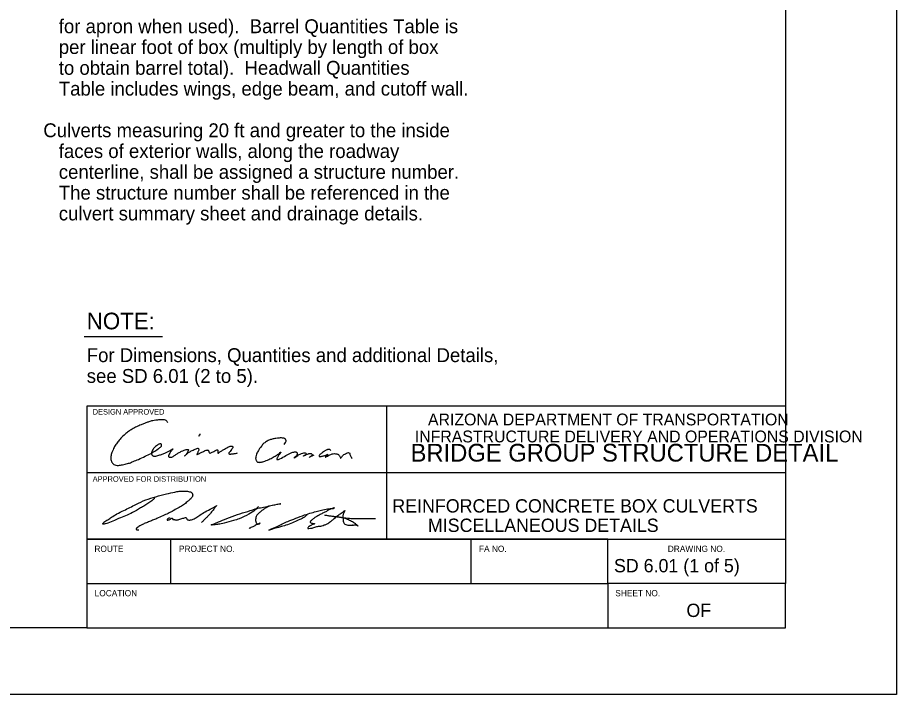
# Model space of a CAD drawing. Extents: x -0.08 to 2.83, y -0.03 to 1.92.
# Drawn here: x 2.009 to 2.833, y 0 to 0.635 of the extents above; entities that cross this region are included whole.
import ezdxf

# ---------------------------------------------------------------- set-up
doc = ezdxf.new("R2010")
doc.units = 0
for name, color, linetype in [('55', 7, 'Continuous'), ('57', 7, 'Continuous'), ('62', 7, 'Continuous'), ('63', 7, 'Continuous')]:
    doc.layers.add(name, color=color, linetype=linetype)

msp = doc.modelspace()

# ---------------------------------------------------------------- linework, layer by layer
at = {"layer": '55'}
for points in [[(2.15001, 0.25543), (2.14758, 0.25741), (2.14617, 0.25785), (2.14423, 0.25794), (2.14225, 0.25776), (2.1402, 0.25761), (2.13722, 0.2572), (2.13461, 0.25674), (2.13312, 0.25633), (2.13139, 0.2557), (2.1309, 0.25548), (2.1279, 0.25446), (2.12484, 0.2532), (2.1206, 0.25132), (2.11648, 0.24906), (2.11297, 0.24683), (2.10987, 0.24445), (2.10588, 0.24062), (2.10299, 0.237), (2.10059, 0.23378), (2.09857, 0.22978), (2.09735, 0.22698), (2.09658, 0.22347), (2.09632, 0.22083), (2.0965, 0.22021), (2.09681, 0.21951), (2.09723, 0.21833), (2.098, 0.21721), (2.09936, 0.21582), (2.101, 0.2152), (2.10355, 0.21505), (2.10736, 0.21566), (2.10994, 0.21625), (2.11399, 0.21726), (2.11746, 0.21865), (2.1224, 0.22067), (2.12858, 0.22356), (2.13414, 0.22632), (2.14122, 0.23075), (2.14355, 0.23265), (2.1438, 0.23291), (2.14403, 0.23351), (2.14403, 0.23426), (2.14395, 0.23467), (2.14366, 0.23506), (2.14306, 0.23523), (2.14231, 0.23519), (2.14138, 0.23496), (2.14015, 0.23417), (2.13831, 0.23262), (2.1366, 0.23096), (2.1355, 0.22937), (2.13485, 0.2278), (2.13469, 0.22641), (2.13471, 0.22546), (2.13499, 0.22483), (2.13551, 0.2243), (2.13614, 0.22393), (2.13712, 0.22378), (2.13865, 0.22378), (2.14061, 0.22424), (2.1439, 0.22538), (2.14709, 0.22656), (2.14964, 0.22791), (2.15235, 0.22918), (2.1548, 0.23064), (2.15321, 0.22863), (2.15278, 0.22814), (2.15212, 0.22718), (2.15124, 0.22569), (2.15055, 0.22402), (2.15062, 0.22327), (2.15113, 0.2227), (2.15171, 0.22264), (2.15353, 0.2229), (2.15492, 0.22351), (2.15731, 0.22511), (2.15997, 0.22683), (2.16276, 0.22826), (2.16513, 0.22931), (2.1672, 0.22997), (2.16877, 0.23003), (2.16885, 0.23001), (2.16905, 0.22994), (2.16916, 0.22971), (2.16921, 0.22923), (2.16902, 0.22873), (2.16846, 0.22743), (2.1677, 0.22608), (2.16569, 0.22382), (2.16628, 0.22431), (2.16828, 0.22641), (2.16883, 0.2268), (2.16988, 0.2275), (2.1711, 0.22812), (2.17281, 0.229), (2.17455, 0.2298), (2.17652, 0.23053), (2.17805, 0.23107), (2.17845, 0.23099), (2.17884, 0.23056), (2.17886, 0.22947), (2.17831, 0.22798), (2.17796, 0.22723), (2.17731, 0.22578), (2.17716, 0.22546), (2.17716, 0.22538), (2.17753, 0.22539), (2.17821, 0.22565), (2.17895, 0.22596), (2.18003, 0.22647), (2.18113, 0.22707), (2.18425, 0.22854), (2.18595, 0.22925), (2.18701, 0.22947), (2.18751, 0.22945), (2.18764, 0.22938), (2.18777, 0.22927), (2.18805, 0.22878), (2.18849, 0.22777), (2.18919, 0.22648), (2.1903, 0.2268), (2.19162, 0.22742), (2.19305, 0.22818), (2.19472, 0.22898), (2.1958, 0.22955), (2.19618, 0.2297), (2.19652, 0.22948), (2.19677, 0.22899), (2.19681, 0.22851), (2.19688, 0.22708), (2.19689, 0.22654), (2.19699, 0.2265), (2.19794, 0.22713), (2.20054, 0.22882), (2.20306, 0.23041), (2.20516, 0.23164), (2.20697, 0.23255), (2.20839, 0.23299), (2.21006, 0.23312), (2.2106, 0.23289), (2.21082, 0.23247), (2.2109, 0.23199), (2.21081, 0.23152), (2.2104, 0.23086), (2.20965, 0.2299), (2.20831, 0.22816), (2.20712, 0.22678), (2.20699, 0.22618), (2.20715, 0.22586), (2.2085, 0.22567), (2.20942, 0.22576), (2.21055, 0.22588), (2.21161, 0.22603), (2.21247, 0.22616), (2.21418, 0.22636), (2.21539, 0.22668)], [(2.17986, 0.24471), (2.17999, 0.24419), (2.17945, 0.24328), (2.17891, 0.24254), (2.18016, 0.24389), (2.18061, 0.24401)], [(2.25913, 0.23472), (2.26029, 0.23637), (2.26076, 0.23774), (2.26076, 0.23856), (2.26062, 0.23911), (2.26004, 0.23992), (2.25945, 0.24026), (2.2583, 0.24058), (2.25644, 0.2408), (2.25422, 0.2407), (2.25114, 0.2404), (2.24777, 0.23963), (2.2448, 0.23864), (2.24155, 0.23685), (2.23882, 0.23456), (2.2377, 0.23304), (2.2365, 0.23153), (2.23482, 0.22905), (2.23317, 0.22562), (2.23251, 0.22313), (2.2323, 0.22157), (2.2325, 0.22061), (2.23275, 0.2199), (2.23334, 0.21882), (2.23414, 0.21819), (2.23498, 0.21801), (2.2361, 0.21789), (2.23696, 0.21795), (2.23781, 0.21809), (2.23899, 0.21844), (2.24106, 0.21913), (2.24338, 0.21998), (2.24568, 0.22106), (2.24791, 0.22222), (2.25148, 0.22431), (2.25408, 0.22593), (2.25528, 0.22699), (2.25596, 0.22758), (2.2558, 0.22724), (2.25569, 0.22701), (2.25442, 0.2253), (2.25333, 0.22375), (2.25269, 0.22234), (2.25245, 0.22167), (2.25221, 0.22097), (2.25221, 0.22077), (2.25227, 0.22059), (2.25263, 0.22047), (2.25298, 0.22053), (2.2536, 0.22067), (2.25502, 0.22125), (2.26074, 0.22419), (2.26545, 0.22673), (2.26732, 0.22736), (2.26877, 0.22774), (2.26999, 0.22768), (2.27076, 0.22738), (2.27111, 0.22675), (2.27112, 0.22556), (2.27102, 0.22481), (2.27061, 0.22411), (2.26819, 0.22181), (2.27093, 0.22373), (2.27398, 0.22556), (2.27644, 0.22654), (2.27843, 0.22689), (2.27927, 0.22661), (2.27985, 0.2258), (2.27977, 0.22554), (2.27976, 0.22537), (2.27941, 0.22518), (2.2786, 0.22453), (2.27706, 0.22375), (2.27972, 0.22513), (2.28179, 0.22589), (2.28256, 0.22619), (2.28403, 0.22629), (2.28469, 0.22599), (2.28517, 0.22525), (2.28515, 0.22471), (2.28492, 0.22428), (2.28393, 0.22344), (2.28235, 0.22249), (2.28532, 0.22412), (2.28733, 0.22492)], [(2.30267, 0.22892), (2.30234, 0.22949), (2.3018, 0.22993), (2.30131, 0.23009), (2.3008, 0.23009), (2.30032, 0.23003), (2.29957, 0.22989), (2.29894, 0.22961), (2.29775, 0.22894), (2.29677, 0.22833), (2.29582, 0.22761), (2.29429, 0.22651), (2.29321, 0.22567), (2.29216, 0.2246), (2.29189, 0.22405), (2.2918, 0.22362), (2.29182, 0.22366), (2.29199, 0.22348), (2.29251, 0.22335), (2.2936, 0.22339), (2.29501, 0.22377), (2.29629, 0.22413), (2.29798, 0.2247), (2.29932, 0.22536), (2.29957, 0.22541), (2.29976, 0.2253), (2.29981, 0.2252), (2.29975, 0.225), (2.29959, 0.2248), (2.29831, 0.22373), (2.29744, 0.22287), (2.29735, 0.22276), (2.29743, 0.2227), (2.29781, 0.22277), (2.2988, 0.22329), (2.30057, 0.22435), (2.30188, 0.225), (2.30392, 0.22573), (2.3061, 0.22604), (2.30849, 0.22581), (2.30949, 0.22544), (2.31036, 0.22475), (2.31091, 0.22411), (2.3116, 0.22265), (2.31196, 0.22161), (2.3126, 0.22233), (2.31334, 0.22346), (2.31434, 0.22457), (2.31582, 0.22566), (2.31756, 0.2264), (2.31949, 0.22699), (2.31976, 0.22691), (2.32023, 0.22668), (2.3207, 0.22516), (2.32126, 0.22398), (2.32189, 0.22286), (2.32233, 0.22209), (2.32292, 0.22145)], [(2.13692, 0.18516), (2.13711, 0.18449), (2.13708, 0.18402), (2.13681, 0.18349), (2.13589, 0.18255), (2.13195, 0.17982), (2.12821, 0.17738), (2.12437, 0.17504), (2.11671, 0.17069), (2.10374, 0.16502), (2.10229, 0.16443), (2.09999, 0.1634), (2.09376, 0.16092), (2.09139, 0.16014), (2.09018, 0.15994), (2.08919, 0.15985), (2.08904, 0.15989), (2.08875, 0.16017), (2.08886, 0.16035), (2.08914, 0.16074), (2.09001, 0.16165), (2.09361, 0.16401), (2.0971, 0.16634), (2.1021, 0.16941), (2.10864, 0.17274), (2.11998, 0.17836), (2.1292, 0.18259), (2.13862, 0.18561), (2.14876, 0.18833), (2.15642, 0.19001), (2.16054, 0.19071), (2.1641, 0.1909), (2.16637, 0.19094), (2.1683, 0.19075), (2.17023, 0.19028), (2.1718, 0.18974), (2.17245, 0.18918), (2.17281, 0.18877), (2.17307, 0.18808), (2.17324, 0.18741), (2.17323, 0.18698), (2.17317, 0.1864), (2.17305, 0.18598), (2.17272, 0.18537), (2.17195, 0.18431), (2.17071, 0.18308), (2.16807, 0.18073), (2.16459, 0.17812), (2.16054, 0.17558), (2.15565, 0.17281), (2.15245, 0.171), (2.14775, 0.16877), (2.14512, 0.16756), (2.13957, 0.16509), (2.1355, 0.16347), (2.13193, 0.16192), (2.12769, 0.16032), (2.12482, 0.15889), (2.12278, 0.15776), (2.12183, 0.1571), (2.12131, 0.15676), (2.12086, 0.15632), (2.12046, 0.15586), (2.12012, 0.15542), (2.12011, 0.15537), (2.12011, 0.15526), (2.1202, 0.15509), (2.12036, 0.15488), (2.12062, 0.15472), (2.12115, 0.15459), (2.12156, 0.15459), (2.12236, 0.15462), (2.12266, 0.15463)], [(2.15215, 0.16533), (2.15165, 0.16558), (2.15087, 0.16542), (2.1497, 0.16466), (2.14918, 0.16411), (2.14918, 0.16383), (2.1495, 0.16362), (2.15043, 0.16388), (2.15113, 0.16407), (2.15248, 0.16463), (2.15357, 0.16535), (2.15403, 0.16543), (2.15418, 0.16544), (2.15443, 0.16515), (2.1544, 0.16455), (2.15476, 0.16431), (2.15544, 0.16432), (2.15619, 0.16415), (2.15697, 0.16398), (2.15772, 0.16378), (2.15893, 0.16383), (2.1601, 0.16421), (2.16212, 0.16481), (2.16403, 0.16537), (2.16566, 0.16582), (2.16712, 0.16606), (2.16767, 0.16496), (2.16804, 0.16429), (2.1689, 0.16384), (2.17004, 0.16347), (2.17128, 0.16384), (2.17298, 0.16426), (2.1762, 0.16591), (2.18, 0.16838), (2.18508, 0.17145), (2.19087, 0.17445), (2.1937, 0.17599), (2.19558, 0.1773), (2.19408, 0.17539), (2.19361, 0.17483), (2.193, 0.17404), (2.19158, 0.17212), (2.19036, 0.17057), (2.18805, 0.16806), (2.18628, 0.16609), (2.18362, 0.16346), (2.18164, 0.16142)], [(2.23491, 0.17651), (2.23186, 0.17315), (2.22584, 0.16918), (2.21679, 0.16499), (2.21159, 0.16321), (2.20276, 0.1609), (2.19747, 0.15972), (2.19293, 0.15912), (2.19072, 0.15909), (2.19235, 0.15989), (2.19737, 0.16193), (2.20515, 0.16517), (2.21517, 0.16888), (2.22498, 0.17188), (2.23419, 0.17479), (2.23965, 0.17583), (2.24639, 0.17729), (2.25314, 0.1786), (2.25576, 0.17906), (2.25005, 0.17775), (2.24376, 0.17607), (2.24298, 0.17572), (2.24203, 0.1753), (2.24067, 0.17435), (2.23819, 0.17259), (2.23585, 0.17076), (2.2335, 0.16821), (2.23281, 0.1669), (2.23236, 0.16519), (2.23225, 0.16307), (2.23247, 0.16233), (2.2327, 0.16154), (2.23327, 0.16046), (2.23374, 0.16008), (2.23426, 0.15985), (2.23515, 0.16001), (2.23578, 0.16029), (2.2364, 0.16088), (2.23548, 0.16053), (2.23352, 0.15952), (2.23198, 0.15863), (2.23092, 0.15801), (2.22859, 0.15697), (2.227, 0.15624), (2.22607, 0.15571)], [(2.28075, 0.16875), (2.27797, 0.16654), (2.27366, 0.16413), (2.26825, 0.16177), (2.26206, 0.15933), (2.25657, 0.15761), (2.25242, 0.15648), (2.24459, 0.1543), (2.24926, 0.15636), (2.25262, 0.1578), (2.25725, 0.16014), (2.26258, 0.16247), (2.26991, 0.16539), (2.27822, 0.16854), (2.28481, 0.17056), (2.29031, 0.17203), (2.29538, 0.17324), (2.30109, 0.17436), (2.30588, 0.17543), (2.30606, 0.17546), (2.30606, 0.17525), (2.30316, 0.17414), (2.3009, 0.17315), (2.29924, 0.17223), (2.29807, 0.17157), (2.29507, 0.17014), (2.29189, 0.16831), (2.28907, 0.16674), (2.28671, 0.16521), (2.28453, 0.16333), (2.28365, 0.16246), (2.28334, 0.16199), (2.28345, 0.1616), (2.28392, 0.16118), (2.28531, 0.16081), (2.28728, 0.16045), (2.28749, 0.16038), (2.28753, 0.16024), (2.28657, 0.15987), (2.2841, 0.15862), (2.28248, 0.15764), (2.2816, 0.15684), (2.28122, 0.15623), (2.28119, 0.15602), (2.28133, 0.15581), (2.28226, 0.15582), (2.28517, 0.15615), (2.28673, 0.1566), (2.28889, 0.15734), (2.29045, 0.15779), (2.29226, 0.15803), (2.29432, 0.15824), (2.29669, 0.15913), (2.29931, 0.16013), (2.30238, 0.16221), (2.30477, 0.16406), (2.30941, 0.16804), (2.31103, 0.1692), (2.31434, 0.17146), (2.31581, 0.17269), (2.31451, 0.16933), (2.31413, 0.1664), (2.31439, 0.16328), (2.31521, 0.16058), (2.31694, 0.1594), (2.32065, 0.15881), (2.32285, 0.15892), (2.32308, 0.15901), (2.32329, 0.15919), (2.32353, 0.15911), (2.32364, 0.159), (2.32467, 0.15907), (2.32563, 0.1593), (2.32699, 0.15903), (2.32804, 0.15819), (2.32817, 0.1581), (2.32825, 0.15812), (2.32825, 0.1582), (2.32813, 0.15837), (2.32721, 0.15911), (2.32701, 0.15927), (2.32506, 0.16076), (2.32392, 0.16151), (2.32032, 0.16332), (2.31627, 0.16522), (2.315, 0.16561), (2.31286, 0.166), (2.30979, 0.16645), (2.30602, 0.16682), (2.30209, 0.16741), (2.29903, 0.16786), (2.29731, 0.16826), (2.30287, 0.16758), (2.31104, 0.16647), (2.31894, 0.16545), (2.32442, 0.16523), (2.33099, 0.16521), (2.3432, 0.1651), (2.34473, 0.16507)]]:
    msp.add_spline(points, degree=3, dxfattribs=at)
at = {"layer": '57'}
msp.add_line((2.07131, 0.33607), (2.14477, 0.33607), dxfattribs=at)
at = {"layer": '63'}
for p, q in [((2.83333, 1.83333), (2.83333, 0)), ((2.72918, 0.27077), (2.07387, 0.27077)), ((2.07387, 0.27077), (2.07387, 0.06244)), ((2.35493, 0.27077), (2.35493, 0.14578)), ((2.57284, 0.27077), (2.57284, 0.27077)), ((2.07387, 0.20828), (2.72918, 0.20828)), ((2.07387, 0.20647), (2.07387, 0.20647)), ((2.07387, 0.20647), (2.07387, 0.20647)), ((2.07387, 0.14578), (2.72918, 0.14578)), ((2.07387, 0.14397), (2.07387, 0.14397)), ((2.08908, 0.14583), (2.08931, 0.14583)), ((2.15266, 0.10411), (2.15266, 0.14578)), ((2.23742, 0.14583), (2.23742, 0.14583)), ((2.23742, 0.14583), (2.23742, 0.14583)), ((2.23742, 0.14583), (2.23742, 0.14583)), ((2.23742, 0.14583), (2.23742, 0.14583)), ((2.43435, 0.10411), (2.43435, 0.14578)), ((2.07387, 0.10411), (2.56251, 0.10411)), ((2.56251, 0.10411), (2.56251, 0.06244)), ((2.72918, 0.06244), (2.72918, 0.10411)), ((2.07387, 0.06244), (2.72918, 0.06244)), ((2.83333, 0), (0, 0)), ((2.83, 0.00033), (2.83, 0.00033))]:
    msp.add_line(p, q, dxfattribs=at)
msp.add_lwpolyline([(0.16668, 0.06244), (0.16668, 1.77077), (2.72918, 1.77077), (2.72918, 0.10411), (2.56251, 0.10411), (2.56251, 0.14578), (2.07387, 0.14578), (2.07387, 0.06244)], close=True, dxfattribs=at)

# ---------------------------------------------------------------- texts
at = {"layer": '55'}
for s, p in [('DESIGN APPROVED', (2.07944, 0.26274)), ('APPROVED FOR DISTRIBUTION', (2.07944, 0.19966))]:
    msp.add_text(s, height=0.0052084, dxfattribs=at).set_placement(p)
at = {"layer": '57'}
for s, height, p in [('   for apron when used).  Barrel Quantities Table is', 0.0130208, (2.03313, 0.62079)), ('   per linear foot of box (multiply by length of box', 0.0130208, (2.03313, 0.60126)), ('   to obtain barrel total).  Headwall Quantities', 0.0130208, (2.03313, 0.58173)), ('   Table includes wings, edge beam, and cutoff wall.', 0.0130208, (2.03313, 0.5622)), ('Culverts measuring 20 ft and greater to the inside', 0.0130208, (2.03313, 0.52313)), ('   faces of exterior walls, along the roadway', 0.0130208, (2.03313, 0.5036)), ('   centerline, shall be assigned a structure number.', 0.0130208, (2.03313, 0.48407)), ('   The structure number shall be referenced in the', 0.0130208, (2.03313, 0.46454)), ('   culvert summary sheet and drainage details.', 0.0130208, (2.03313, 0.44501)), ('NOTE:', 0.015625, (2.07387, 0.34278)), ('For Dimensions, Quantities and additional Details,', 0.0130208, (2.07387, 0.31201)), ('see SD 6.01 (2 to 5).', 0.0130208, (2.07387, 0.29248))]:
    msp.add_text(s, height=height, dxfattribs=at).set_placement(p)
at = {"layer": '62'}
for s, p in [('REINFORCED CONCRETE BOX CULVERTS', (2.3605, 0.17078)), ('      MISCELLANEOUS DETAILS     ', (2.36601, 0.15255)), ('SD 6.01 (1 of 5)', (2.56838, 0.11464))]:
    msp.add_text(s, height=0.0125, dxfattribs=at).set_placement(p)
at = {"layer": '63'}
for s, height, p in [('ARIZONA DEPARTMENT OF TRANSPORTATION', 0.0111083, (2.39394, 0.25258)), ('INFRASTRUCTURE DELIVERY AND OPERATIONS DIVISION', 0.0111083, (2.38162, 0.23663)), ('BRIDGE GROUP STRUCTURE DETAIL', 0.0166667, (2.37762, 0.2186)), ('ROUTE', 0.005833, (2.08105, 0.13383)), ('PROJECT NO.', 0.0058333, (2.16034, 0.13383)), ('FA NO.', 0.005833, (2.44175, 0.13383)), ('DRAWING NO.', 0.0058334, (2.61888, 0.13383)), ('LOCATION', 0.005833, (2.08128, 0.09217)), ('SHEET NO.', 0.005833, (2.56964, 0.09217)), ('OF', 0.0125, (2.63638, 0.0727))]:
    msp.add_text(s, height=height, dxfattribs=at).set_placement(p)

doc.saveas('drawing.dxf')
